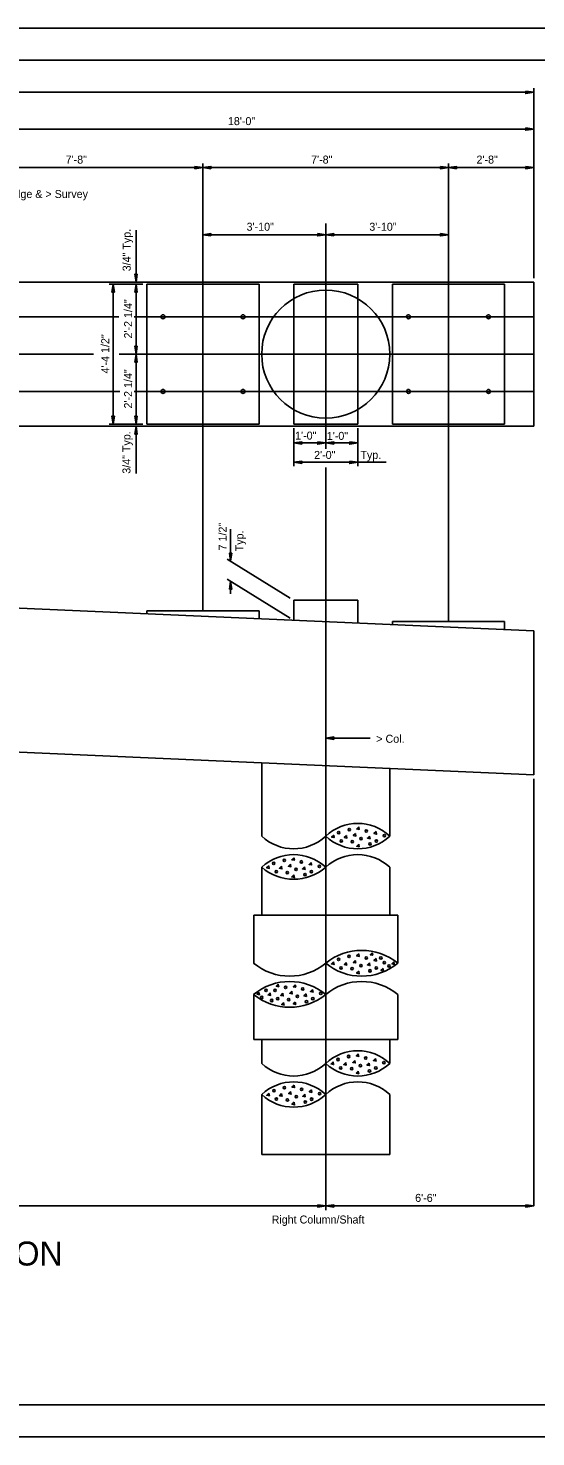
# Model space of a CAD drawing. Extents: x -437.9 to -365.7, y 404.2 to 448.2.
# Drawn here: x -408.12 to -392.26, y 404.21 to 448.22 of the extents above; entities that cross this region are included whole.
import ezdxf

# ---------------------------------------------------------------- set-up
doc = ezdxf.new("R2010")
doc.units = 0
for name, color, linetype in [('BR_AUTO DIMENSION', 7, 'Continuous'), ('BR_BORDER LINES', 7, 'Continuous'), ('BR_CENTER LINES', 7, 'Continuous'), ('BR_CONCRETE', 7, 'Continuous'), ('BR_REBAR', 7, 'Continuous'), ('BR_TEXT', 7, 'Continuous'), ('RD_SHT_IplotShp', 7, 'Continuous')]:
    doc.layers.add(name, color=color, linetype=linetype)

msp = doc.modelspace()

# ---------------------------------------------------------------- linework, layer by layer
at = {"layer": 'BR_AUTO DIMENSION'}
for p, q in [((-428.327, 446.213), (-392.327, 446.213)), ((-392.327, 445.179), (-392.327, 446.338)), ((-410.327, 445.063), (-392.327, 445.063)), ((-392.327, 443.986), (-392.327, 445.188)), ((-392.327, 440.409), (-392.327, 445.179)), ((-392.327, 440.409), (-392.327, 445.179)), ((-410.327, 443.861), (-402.66, 443.861)), ((-402.66, 443.861), (-394.993, 443.861)), ((-394.993, 443.861), (-392.327, 443.861)), ((-404.749, 441.907), (-404.749, 440.284)), ((-402.66, 441.763), (-398.827, 441.763)), ((-398.827, 441.763), (-394.993, 441.763)), ((-404.749, 440.618), (-404.749, 440.284)), ((-404.534, 440.222), (-405.589, 440.222)), ((-405.464, 440.222), (-405.464, 435.847)), ((-404.535, 440.222), (-404.874, 440.222)), ((-404.749, 440.222), (-404.749, 435.847)), ((-404.534, 435.847), (-405.589, 435.847)), ((-404.874, 435.847), (-405.447, 435.847)), ((-404.749, 435.784), (-404.749, 434.303)), ((-399.827, 435.722), (-399.827, 435.133)), ((-399.827, 435.722), (-399.827, 434.529)), ((-397.827, 435.722), (-397.827, 434.529)), ((-397.827, 435.722), (-397.827, 435.133)), ((-399.827, 435.258), (-397.827, 435.258)), ((-399.827, 434.654), (-396.934, 434.654)), ((-401.796, 432.563), (-401.796, 431.563)), ((-399.933, 430.411), (-401.903, 431.629)), ((-399.933, 429.788), (-401.903, 431.006)), ((-401.796, 430.545), (-401.796, 430.94)), ((-397.443, 426.036), (-398.827, 426.036)), ((-392.327, 424.768), (-392.327, 411.427)), ((-428.327, 411.427), (-398.827, 411.427)), ((-398.827, 411.427), (-392.327, 411.427)), ((-398.827, 411.302), (-398.827, 411.302))]:
    msp.add_line(p, q, dxfattribs=at)
for points in [[(-392.577, 446.25), (-392.327, 446.213), (-392.577, 446.175)], [(-392.577, 445.1), (-392.327, 445.063), (-392.577, 445.025)], [(-402.91, 443.899), (-402.66, 443.861), (-402.91, 443.824)], [(-402.41, 443.824), (-402.66, 443.861), (-402.41, 443.899)], [(-395.243, 443.899), (-394.993, 443.861), (-395.243, 443.824)], [(-394.743, 443.824), (-394.993, 443.861), (-394.743, 443.899)], [(-392.577, 443.899), (-392.327, 443.861), (-392.577, 443.824)], [(-402.41, 441.725), (-402.66, 441.763), (-402.41, 441.8)], [(-399.077, 441.8), (-398.827, 441.763), (-399.077, 441.725)], [(-398.577, 441.725), (-398.827, 441.763), (-398.577, 441.8)], [(-395.243, 441.8), (-394.993, 441.763), (-395.243, 441.725)], [(-404.712, 440.534), (-404.749, 440.284), (-404.787, 440.534)], [(-405.502, 439.972), (-405.464, 440.222), (-405.427, 439.972)], [(-404.787, 439.972), (-404.749, 440.222), (-404.712, 439.972)], [(-404.712, 438.284), (-404.749, 438.034), (-404.787, 438.284)], [(-404.787, 437.784), (-404.749, 438.034), (-404.712, 437.784)], [(-405.427, 436.097), (-405.464, 435.847), (-405.502, 436.097)], [(-404.712, 436.097), (-404.749, 435.847), (-404.787, 436.097)], [(-404.787, 435.534), (-404.749, 435.784), (-404.712, 435.534)], [(-399.577, 435.22), (-399.827, 435.258), (-399.577, 435.295)], [(-399.077, 435.295), (-398.827, 435.258), (-399.077, 435.22)], [(-398.577, 435.22), (-398.827, 435.258), (-398.577, 435.295)], [(-398.077, 435.295), (-397.827, 435.258), (-398.077, 435.22)], [(-399.577, 434.616), (-399.827, 434.654), (-399.577, 434.691)], [(-398.077, 434.691), (-397.827, 434.654), (-398.077, 434.616)], [(-401.759, 431.813), (-401.796, 431.563), (-401.834, 431.813)], [(-401.834, 430.69), (-401.796, 430.94), (-401.759, 430.69)], [(-398.575, 425.994), (-398.827, 426.036), (-398.575, 426.078)], [(-399.077, 411.465), (-398.827, 411.427), (-399.077, 411.39)], [(-398.577, 411.39), (-398.827, 411.427), (-398.577, 411.465)], [(-392.577, 411.465), (-392.327, 411.427), (-392.577, 411.39)]]:
    msp.add_lwpolyline(points, close=True, dxfattribs=at)
at = {"layer": 'BR_BORDER LINES'}
for p, q in [((-437.931, 448.216), (-365.931, 448.216)), ((-366.931, 447.213), (-434.265, 447.213)), ((-434.265, 405.213), (-366.931, 405.213))]:
    msp.add_line(p, q, dxfattribs=at)
at = {"layer": 'BR_CENTER LINES'}
for p, q in [((-402.66, 430.014), (-402.66, 443.985)), ((-394.993, 429.677), (-394.993, 443.985)), ((-398.827, 435.079), (-398.827, 442.116)), ((-429.984, 439.201), (-405.292, 439.201)), ((-404.808, 439.201), (-392.327, 439.201)), ((-428.985, 438.034), (-406.082, 438.034)), ((-405.282, 438.034), (-392.327, 438.034)), ((-429.962, 436.868), (-405.254, 436.868)), ((-404.808, 436.868), (-392.327, 436.868)), ((-398.827, 411.294), (-398.827, 434.494))]:
    msp.add_line(p, q, dxfattribs=at)
at = {"layer": 'BR_CONCRETE'}
for p, q in [((-428.327, 440.284), (-392.327, 440.284)), ((-404.41, 440.222), (-400.91, 440.222)), ((-404.41, 435.847), (-404.41, 440.222)), ((-400.91, 440.222), (-400.91, 435.847)), ((-399.827, 440.222), (-397.827, 440.222)), ((-399.827, 440.222), (-399.827, 435.847)), ((-397.827, 435.847), (-397.827, 440.222)), ((-396.743, 440.222), (-393.243, 440.222)), ((-396.743, 435.847), (-396.743, 440.222)), ((-393.243, 440.222), (-393.243, 435.847)), ((-392.327, 440.284), (-392.327, 435.784)), ((-428.327, 435.784), (-392.327, 435.784)), ((-400.91, 435.847), (-404.41, 435.847)), ((-399.827, 435.847), (-397.827, 435.847)), ((-393.243, 435.847), (-396.743, 435.847)), ((-428.327, 430.977), (-392.327, 429.393)), ((-404.41, 429.924), (-404.41, 430.014)), ((-404.41, 430.014), (-400.91, 430.014)), ((-400.91, 430.014), (-400.91, 429.77)), ((-399.827, 430.345), (-397.827, 430.345)), ((-399.827, 430.345), (-399.827, 429.723)), ((-397.827, 429.635), (-397.827, 430.345)), ((-396.743, 429.587), (-396.743, 429.677)), ((-396.743, 429.677), (-393.243, 429.677)), ((-393.243, 429.677), (-393.243, 429.433)), ((-392.327, 429.393), (-392.327, 424.893)), ((-428.327, 426.477), (-392.327, 424.893)), ((-400.827, 425.267), (-400.827, 422.977)), ((-396.827, 425.091), (-396.827, 422.977)), ((-400.827, 422.006), (-400.827, 420.506)), ((-396.827, 422.006), (-396.827, 420.506)), ((-401.077, 420.506), (-396.577, 420.506)), ((-401.077, 420.506), (-401.077, 419.006)), ((-396.577, 420.506), (-396.577, 419.006)), ((-401.077, 416.627), (-401.077, 418.034)), ((-396.577, 416.627), (-396.577, 418.034)), ((-401.077, 416.627), (-396.577, 416.627)), ((-400.827, 416.627), (-400.827, 415.877)), ((-396.827, 416.627), (-396.827, 415.877)), ((-400.827, 414.906), (-400.827, 413.031)), ((-396.827, 414.906), (-396.827, 413.031)), ((-400.827, 413.031), (-396.827, 413.031))]:
    msp.add_line(p, q, dxfattribs=at)
msp.add_circle((-398.827, 438.034), 2, dxfattribs=at)
for centre, radius, start, end in [((-397.827, 421.912), 1.461, 46.811, 133.189), ((-399.827, 424.042), 1.461, 226.811, 313.189), ((-397.827, 424.042), 1.461, 226.811, 313.189), ((-399.827, 420.94), 1.461, 46.811, 133.189), ((-399.827, 423.14), 1.512, 228.6075, 311.3925), ((-397.827, 420.94), 1.461, 46.811, 133.189), ((-397.702, 417.633), 1.775, 50.6575, 129.3425), ((-399.952, 420.378), 1.775, 230.6575, 309.3425), ((-397.702, 420.378), 1.775, 230.6575, 309.3425), ((-399.952, 416.662), 1.775, 50.6575, 129.3425), ((-399.952, 419.407), 1.775, 230.6575, 309.3425), ((-397.702, 416.662), 1.775, 50.6575, 129.3425), ((-397.827, 414.812), 1.461, 46.811, 133.189), ((-399.827, 416.943), 1.461, 226.811, 313.189), ((-397.827, 416.943), 1.461, 226.811, 313.189), ((-399.827, 413.841), 1.461, 46.811, 133.189), ((-397.827, 413.841), 1.461, 46.811, 133.189), ((-399.827, 415.971), 1.461, 226.811, 313.189)]:
    msp.add_arc(centre, radius, start, end, dxfattribs=at)
at = {"layer": 'BR_REBAR'}
for points in [[(-398.578, 423.011), (-398.563, 422.931), (-398.644, 422.949)], [(-398.181, 422.997), (-398.166, 422.916), (-398.247, 422.934)], [(-397.899, 423.061), (-397.885, 422.981), (-397.966, 422.999)], [(-397.791, 423.265), (-397.777, 423.185), (-397.857, 423.203)], [(-397.457, 422.979), (-397.443, 422.898), (-397.524, 422.916)], [(-397.252, 423.118), (-397.238, 423.038), (-397.319, 423.056)], [(-397.791, 422.726), (-397.777, 422.645), (-397.857, 422.663)], [(-400.606, 422.05), (-400.592, 421.97), (-400.672, 421.988)], [(-400.209, 422.035), (-400.195, 421.955), (-400.275, 421.973)], [(-399.927, 422.1), (-399.913, 422.02), (-399.994, 422.038)], [(-399.819, 422.304), (-399.805, 422.223), (-399.886, 422.242)], [(-399.485, 422.018), (-399.471, 421.937), (-399.552, 421.955)], [(-399.281, 422.157), (-399.267, 422.076), (-399.347, 422.095)], [(-399.819, 421.765), (-399.805, 421.684), (-399.886, 421.702)], [(-398.58, 419.047), (-398.566, 418.966), (-398.647, 418.984)], [(-398.183, 419.032), (-398.169, 418.951), (-398.25, 418.97)], [(-397.902, 419.097), (-397.888, 419.016), (-397.968, 419.034)], [(-397.793, 419.301), (-397.779, 419.22), (-397.86, 419.238)], [(-397.46, 419.015), (-397.446, 418.934), (-397.526, 418.952)], [(-397.372, 419.335), (-397.358, 419.254), (-397.438, 419.272)], [(-397.255, 419.154), (-397.241, 419.073), (-397.322, 419.091)], [(-396.695, 419.051), (-396.681, 418.97), (-396.761, 418.988)], [(-397.793, 418.762), (-397.779, 418.681), (-397.86, 418.699)], [(-397.036, 418.844), (-397.022, 418.763), (-397.103, 418.781)], [(-400.911, 418.103), (-400.897, 418.023), (-400.978, 418.041)], [(-400.562, 418.082), (-400.548, 418.001), (-400.629, 418.019)], [(-400.308, 418.351), (-400.293, 418.27), (-400.374, 418.288)], [(-400.165, 418.067), (-400.151, 417.986), (-400.232, 418.004)], [(-399.884, 418.132), (-399.87, 418.051), (-399.95, 418.069)], [(-399.776, 418.336), (-399.762, 418.255), (-399.842, 418.273)], [(-399.442, 418.049), (-399.428, 417.969), (-399.509, 417.987)], [(-399.237, 418.189), (-399.223, 418.108), (-399.304, 418.126)], [(-400.14, 417.78), (-400.126, 417.699), (-400.206, 417.717)], [(-399.776, 417.796), (-399.762, 417.716), (-399.842, 417.734)], [(-398.594, 415.922), (-398.58, 415.841), (-398.661, 415.86)], [(-398.197, 415.907), (-398.183, 415.826), (-398.264, 415.845)], [(-397.916, 415.972), (-397.902, 415.891), (-397.983, 415.91)], [(-397.808, 416.176), (-397.794, 416.095), (-397.874, 416.113)], [(-397.474, 415.89), (-397.46, 415.809), (-397.541, 415.827)], [(-397.269, 416.029), (-397.255, 415.948), (-397.336, 415.966)], [(-397.808, 415.637), (-397.794, 415.556), (-397.874, 415.574)], [(-400.6, 414.948), (-400.586, 414.867), (-400.667, 414.885)], [(-399.922, 414.998), (-399.908, 414.917), (-399.988, 414.935)], [(-399.813, 415.201), (-399.799, 415.121), (-399.88, 415.139)], [(-399.275, 415.054), (-399.261, 414.974), (-399.342, 414.992)], [(-400.203, 414.933), (-400.189, 414.852), (-400.27, 414.87)], [(-399.813, 414.662), (-399.799, 414.581), (-399.88, 414.6)], [(-399.48, 414.915), (-399.466, 414.834), (-399.546, 414.853)]]:
    msp.add_lwpolyline(points, close=True, dxfattribs=at)
for centre, radius in [((-403.91, 439.201), 0.0625), ((-401.41, 439.201), 0.0625), ((-396.243, 439.201), 0.0625), ((-393.743, 439.201), 0.0625), ((-403.91, 436.868), 0.0625), ((-401.41, 436.868), 0.0625), ((-396.243, 436.868), 0.0625), ((-393.743, 436.868), 0.0625), ((-398.422, 423.089), 0.0373), ((-398.093, 423.183), 0.0373), ((-397.724, 422.9), 0.0373), ((-397.56, 423.136), 0.0373), ((-396.994, 422.993), 0.0373), ((-398.342, 422.826), 0.0373), ((-397.998, 422.801), 0.0373), ((-397.442, 422.735), 0.0373), ((-397.244, 422.825), 0.0373), ((-400.45, 422.128), 0.0373), ((-400.121, 422.222), 0.0373), ((-399.588, 422.174), 0.0373), ((-399.022, 422.032), 0.0373), ((-400.37, 421.865), 0.0373), ((-400.027, 421.84), 0.0373), ((-399.753, 421.939), 0.0373), ((-399.47, 421.774), 0.0373), ((-399.272, 421.864), 0.0373), ((-398.424, 419.125), 0.0373), ((-398.096, 419.219), 0.0373), ((-397.727, 418.935), 0.0373), ((-397.562, 419.171), 0.0373), ((-397.105, 419.171), 0.0373), ((-396.997, 419.029), 0.0373), ((-396.846, 418.921), 0.0373), ((-398.345, 418.861), 0.0373), ((-398.001, 418.836), 0.0373), ((-397.444, 418.77), 0.0373), ((-397.246, 418.861), 0.0373), ((-400.688, 418.16), 0.0373), ((-400.407, 418.159), 0.0373), ((-400.078, 418.253), 0.0373), ((-399.545, 418.206), 0.0373), ((-398.979, 418.064), 0.0373), ((-400.826, 417.937), 0.0373), ((-400.514, 417.843), 0.0373), ((-400.327, 417.896), 0.0373), ((-399.983, 417.871), 0.0373), ((-399.709, 417.97), 0.0373), ((-399.427, 417.805), 0.0373), ((-399.229, 417.896), 0.0373), ((-398.439, 416), 0.0373), ((-398.11, 416.094), 0.0373), ((-397.741, 415.81), 0.0373), ((-397.577, 416.046), 0.0373), ((-397.011, 415.904), 0.0373), ((-398.359, 415.736), 0.0373), ((-398.015, 415.711), 0.0373), ((-397.459, 415.645), 0.0373), ((-397.261, 415.736), 0.0373), ((-400.444, 415.025), 0.0373), ((-400.116, 415.119), 0.0373), ((-399.582, 415.072), 0.0373), ((-399.017, 414.929), 0.0373), ((-400.365, 414.762), 0.0373), ((-400.021, 414.737), 0.0373), ((-399.747, 414.836), 0.0373), ((-399.464, 414.671), 0.0373), ((-399.266, 414.761), 0.0373)]:
    msp.add_circle(centre, radius, dxfattribs=at)
at = {"layer": 'RD_SHT_IplotShp'}
for p, q in [((-437.931, 448.213), (-365.931, 448.213)), ((-365.931, 404.213), (-437.931, 404.213))]:
    msp.add_line(p, q, dxfattribs=at)

# ---------------------------------------------------------------- texts
at = {"layer": 'BR_TEXT'}
for s, height, p in [('18\'-0"', 0.25, (-401.881, 445.188)), ('7\'-8"', 0.25, (-406.95, 443.986)), ('7\'-8"', 0.25, (-399.283, 443.986)), ('2\'-8"', 0.25, (-394.117, 443.986)), ('> Bridge & > Survey', 0.25, (-409.244, 442.912)), ('3\'-10"', 0.25, (-401.298, 441.888)), ('3\'-10"', 0.25, (-397.465, 441.888)), ('1\'-0"', 0.25, (-399.783, 435.364)), ('1\'-0"', 0.25, (-398.793, 435.355)), ('2\'-0"', 0.25, (-399.189, 434.76)), (' Typ.', 0.25, (-397.835, 434.761)), ('> Col.', 0.25, (-397.247, 425.894)), ('6\'-6"', 0.25, (-396.033, 411.552)), ('Right Column/Shaft', 0.25, (-400.516, 410.876)), ('ELEVATION', 0.75, (-412.671, 409.564))]:
    msp.add_text(s, height=height, dxfattribs=at).set_placement(p)
for s, p in [('3/4" Typ.', (-404.919, 440.621)), ('2\'-2 1/4"', (-404.874, 438.523)), ('4\'-4 1/2"', (-405.589, 437.43)), ('2\'-2 1/4"', (-404.874, 436.336)), ('3/4" Typ.', (-404.925, 434.298)), ('7 1/2"', (-401.921, 431.903)), ('Typ.', (-401.396, 431.874))]:
    msp.add_text(s, height=0.25, rotation=90, dxfattribs=at).set_placement(p)

doc.saveas('drawing.dxf')
